Omron CX-Programmer project NuevoProyecto (CX-Programmer 9.50)

# PLC NewPLC1: CP1L-E EM

## Program P18 (cyclic task 0)
Local symbols
EV1 100.01 BOOL
EV2 100.02 BOOL
EV3 100.03 BOOL
Etapa_10 10.00 BOOL
Etapa_11 10.01 BOOL
Etapa_12 10.02 BOOL
Etapa_13 10.03 BOOL
Etapa_14 10.04 BOOL
Etapa_15 10.05 BOOL
Etapa_16 10.06 BOOL
Etapa_20 20.00 BOOL
Etapa_21 20.01 BOOL
Etapa_22 20.02 BOOL
Etapa_23 20.03 BOOL
Etapa_24 20.04 BOOL
Etapa_25 20.05 BOOL
Etapa_26 20.06 BOOL
Etapa_27 20.07 BOOL
F1 0.02 BOOL
FSF1 15.00 BOOL  ; Flanco Subida F1
MC 100.00 BOOL
S_1 0.01 BOOL
m 0.00 BOOL

### Section Sección1_Programa_principal
; Programa principal (Etapas 10 ... 16 + Etapas 20 ... 27)

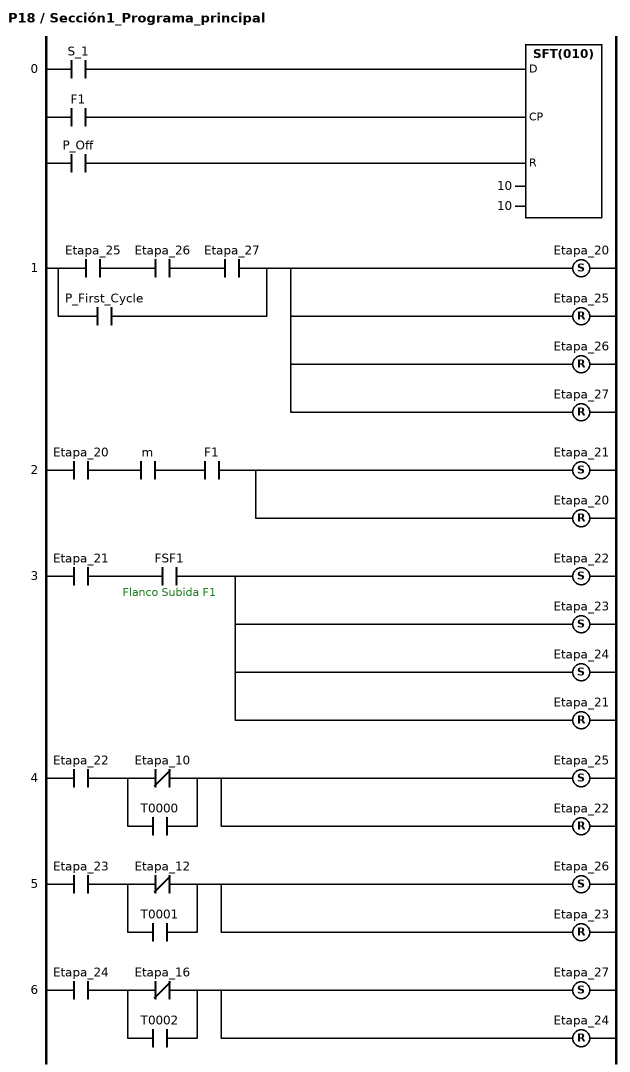
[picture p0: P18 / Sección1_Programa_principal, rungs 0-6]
; rung 0
LD S_1
LD F1  // No hace falta que F1 se programe como FSF1 ya que el registro se desplaza cada vez que F1 pasa de 0 a 1
LD P_Off
SFT(010) 10 10  // Las Etapas 10 ... 16 estan contenidas en el registro de desplazamiento
; rung 1
LD Etapa_25
AND Etapa_26
AND Etapa_27
OR P_First_Cycle
SET Etapa_20
RSET Etapa_25
RSET Etapa_26
RSET Etapa_27
; rung 2
LD Etapa_20
AND m
AND F1
SET Etapa_21
RSET Etapa_20
; rung 3
LD Etapa_21
AND FSF1  ; Flanco Subida F1
SET Etapa_22
SET Etapa_23
SET Etapa_24
RSET Etapa_21
; rung 4
LD Etapa_22
LDNOT Etapa_10
OR T0000
ANDLD
SET Etapa_25
RSET Etapa_22
; rung 5
LD Etapa_23
LDNOT Etapa_12
OR T0001
ANDLD
SET Etapa_26
RSET Etapa_23
; rung 6
LD Etapa_24
LDNOT Etapa_16
OR T0002
ANDLD
SET Etapa_27
RSET Etapa_24

### Section Sección2_Temporizadores

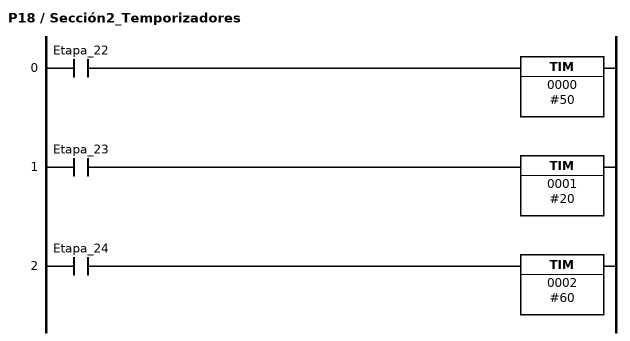
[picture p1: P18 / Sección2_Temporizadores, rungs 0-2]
; rung 0
LD Etapa_22
TIM 0000 #50
; rung 1
LD Etapa_23
TIM 0001 #20
; rung 2
LD Etapa_24
TIM 0002 #60

### Section Sección3_FSF1

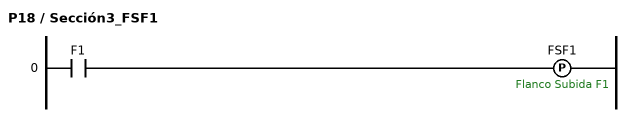
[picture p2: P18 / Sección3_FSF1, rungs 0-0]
; rung 0
LD F1
DIFU(013) FSF1  ; Flanco Subida F1

### Section Sección4_Salidas

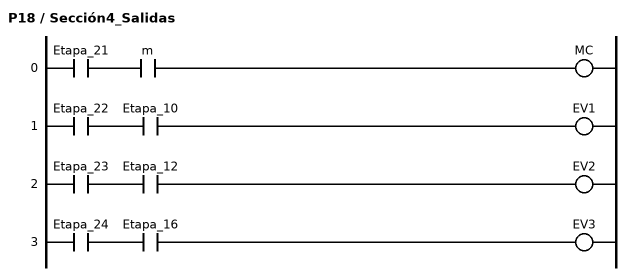
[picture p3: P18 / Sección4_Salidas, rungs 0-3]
; rung 0
LD Etapa_21
AND m
OUT MC
; rung 1
LD Etapa_22
AND Etapa_10
OUT EV1
; rung 2
LD Etapa_23
AND Etapa_12
OUT EV2
; rung 3
LD Etapa_24
AND Etapa_16
OUT EV3

### Section Sección5_END
; rung 0: Fin de programa
END(001)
